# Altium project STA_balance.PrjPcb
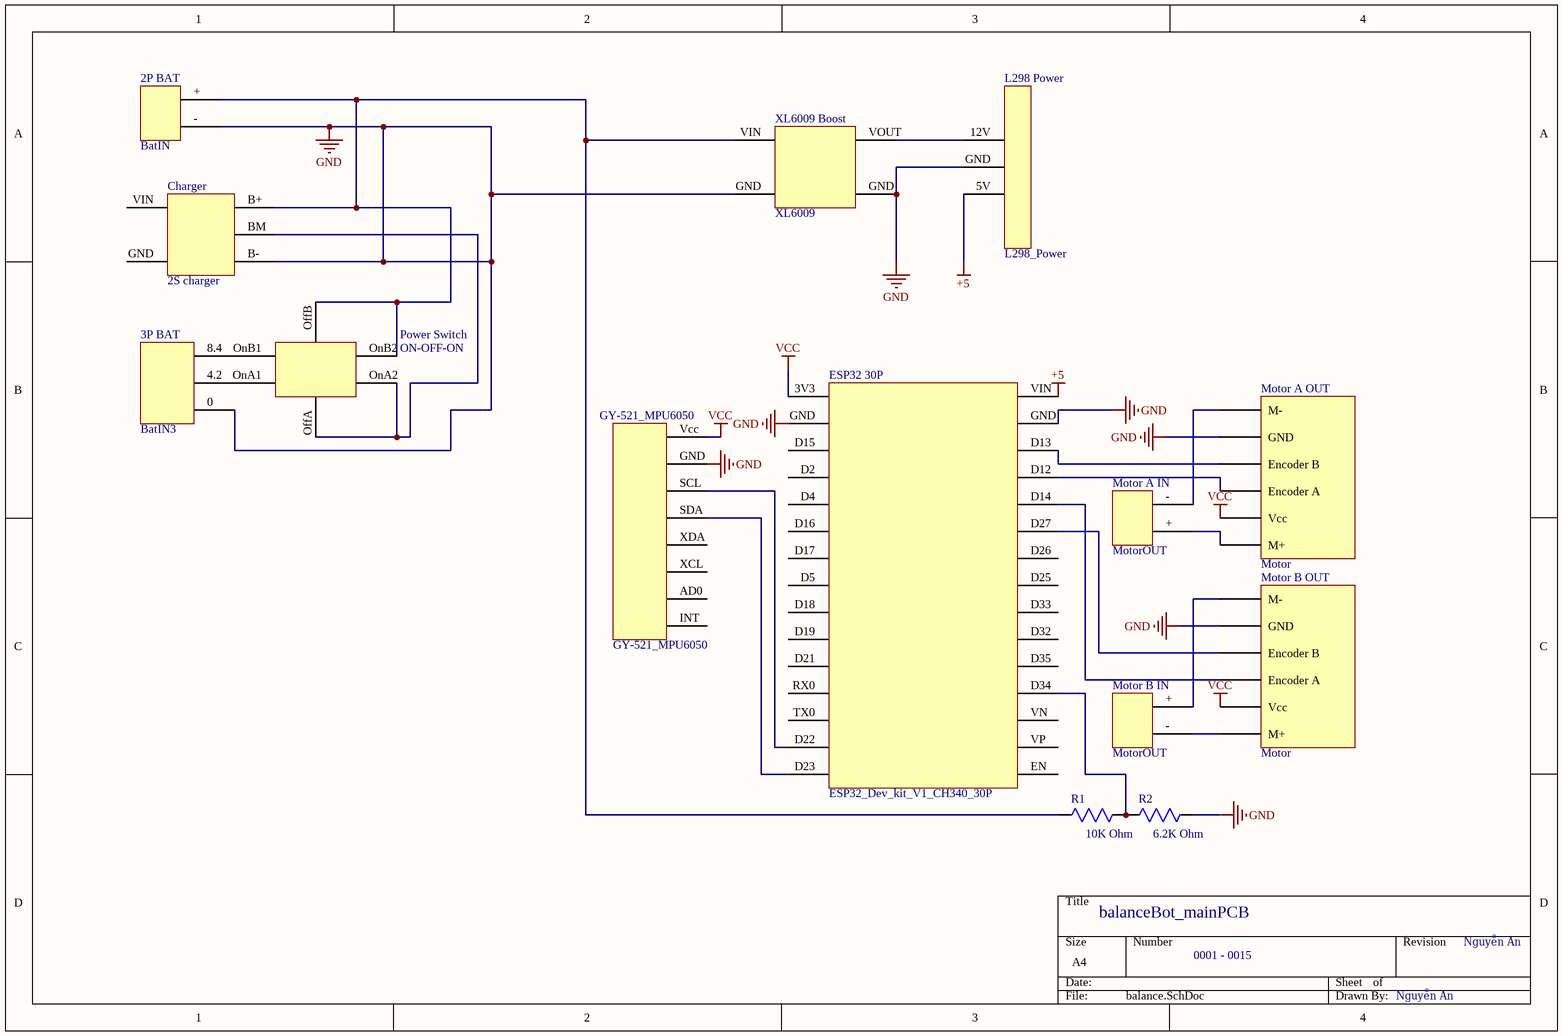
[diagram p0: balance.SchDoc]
1 sheet, 14 parts. Net scope: global (net labels, ports and power ports of the same name join across sheets).
Board file: balance.PcbDoc

## Sheet balance.SchDoc: balanceBot_mainPCB
size A4; Date: 25/4/2025; Author: Nguyễn An; DrawnBy: Nguyễn An; SheetNumber: 1; SheetTotal: 1

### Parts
2P_BAT  BatIN  [BatIN]
3P_BAT  BatIN3  [BatIN3]
Charger  2S charger  [2S_charge]
ESP32_30P  ESP32_Dev_kit_V1_CH340_30P  [ESP32]
GY-521_MPU6050  GY-521_MPU6050  [GY-521_MPU6050]
L298_Power  L298_Power  [L298N_POWER]
Motor_A_IN  MotorOUT  [MotorOUT]
Motor_A_OUT  Motor  [Motor]
Motor_B_IN  MotorOUT  [MotorOUT]
Motor_B_OUT  Motor  [Motor]
Power_Switch  ON-OFF-ON  [ON-OFF-ON]
R1  Resistance: 10K Ohm  [RES_0805_SMD]  (hidden comment: RES_0805_SMD)
R2  Resistance: 6.2K Ohm  [RES_0805_SMD]  (hidden comment: RES_0805_SMD)
XL6009_Boost  XL6009  [XL6009]

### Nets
+5: ESP32_30P.VIN L298_Power.5V
GND: 2P_BAT.- 3P_BAT.0 Charger.B- ESP32_30P.GND GY-521_MPU6050.GND L298_Power.GND Motor_A_OUT.GND Motor_B_OUT.GND R2.2 XL6009_Boost.GND
VCC: ESP32_30P.3V3 GY-521_MPU6050.Vcc Motor_A_OUT.Vcc Motor_B_OUT.Vcc
Net2P_BAT_+: 2P_BAT.+ Charger.B+ Power_Switch.OffB Power_Switch.OnB2 R1.1 XL6009_Boost.VIN
Net3P_BAT_4.2: 3P_BAT.4.2 Power_Switch.OnA1
Net3P_BAT_8.4: 3P_BAT.8.4 Power_Switch.OnB1
NetCharger_BM: Charger.BM Power_Switch.OffA Power_Switch.OnA2
NetESP32_30P_D12: ESP32_30P.D12 Motor_A_OUT.Encoder_A
NetESP32_30P_D13: ESP32_30P.D13 Motor_A_OUT.Encoder_B
NetESP32_30P_D14: ESP32_30P.D14 Motor_B_OUT.Encoder_A
NetESP32_30P_D22: ESP32_30P.D22 GY-521_MPU6050.SCL
NetESP32_30P_D23: ESP32_30P.D23 GY-521_MPU6050.SDA
NetESP32_30P_D27: ESP32_30P.D27 Motor_B_OUT.Encoder_B
NetESP32_30P_D34: ESP32_30P.D34 R1.2 R2.1
NetL298_Power_12V: L298_Power.12V XL6009_Boost.VOUT
NetMotor_A_IN_+: Motor_A_IN.+ Motor_A_OUT.M+
NetMotor_A_IN_-: Motor_A_IN.- Motor_A_OUT.M-
NetMotor_B_IN_+: Motor_B_IN.+ Motor_B_OUT.M-
NetMotor_B_IN_-: Motor_B_IN.- Motor_B_OUT.M+

Not connected (* = marked no-connect by the designer): Charger GND VIN; ESP32_30P D2 D4 D5 D15 D16 D17 D18 D19 D21 D25 D26 D32 D33 D35 EN RX0 TX0 VN VP; GY-521_MPU6050 AD0 INT XCL XDA

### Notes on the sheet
- 0001 - 0015

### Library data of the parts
Motor_A_OUT Motor_B_OUT = Motor: Motor with encoder
R1 R2 = CMP-00003-7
